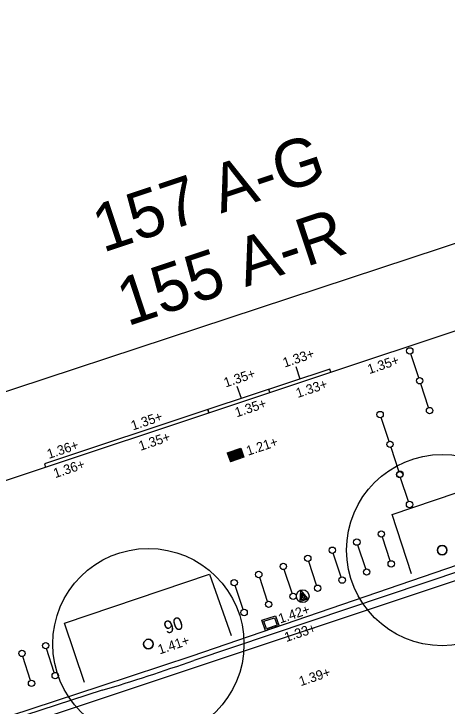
# Model space of a CAD drawing. Extents: x 122462 to 123306, y 485548 to 486417.
# Drawn here: x 122686.41 to 122700.01, y 486146.23 to 486167.94 of the extents above; entities that cross this region are included whole.
import ezdxf

# ---------------------------------------------------------------- set-up
doc = ezdxf.new("R2010")
doc.units = 0
for name, color, linetype in [('B-WE-AL-WERKGRENS-G', 7, 'Continuous'), ('B-WE-GR-BOOM-S', 7, 'Continuous'), ('B-WE-GR-BOOM_BOOMDIAMETER', 7, 'Continuous'), ('B-WE-IE-MEUBILAIR_WEGMEUBILAIR-S', 7, 'Continuous'), ('B-WE-IE-MEUBILAIR_WEGMEUBILAIR_FIETSNIETJE-S', 7, 'Continuous'), ('B-WE-OG-BEBOUWING_PORTIEK1-G', 7, 'Continuous'), ('B-WE-OG-BEBOUWING_RAAM-G', 7, 'Continuous'), ('B-WE-OG-HOOGTEPUNT-S', 7, 'Continuous'), ('B-WE-OG-TOPOKAART-G', 7, 'Continuous'), ('B-WE-RI-HWA_KOLK-S', 7, 'Continuous'), ('B-WE-VH-KANTOPSLUITING_OPSLUITBAND_100X200-G', 7, 'Continuous'), ('B-WE-VH-KANTOPSLUITING_TROTTOIRBAND_180 200-G', 7, 'Continuous'), ('B-WE-VH-MATERIAALGRENS_ASFALT-G', 7, 'Continuous'), ('B-WE-VW-MARKERING_LANGS_STREEP_11_010-G', 7, 'Continuous'), ('Level 58', 7, 'Continuous')]:
    doc.layers.add(name, color=color, linetype=linetype)

msp = doc.modelspace()

# ---------------------------------------------------------------- linework, layer by layer
at = {"layer": 'B-WE-AL-WERKGRENS-G'}
msp.add_lwpolyline([(122857.632, 486078.279), (122830.484, 486160.606), (122900.937, 486183.81), (122887.855, 486222.555), (122665.445, 486149.273), (122678.196, 486110.449), (122807.072, 486152.895), (122835.324, 486068.154)], dxfattribs=at)
at = {"layer": 'B-WE-GR-BOOM-S'}
for centre, radius in [((122699.849, 486151.122), 3), ((122690.629, 486148.177), 3), ((122699.849, 486151.122), 0.15), ((122690.629, 486148.177), 0.15)]:
    msp.add_circle(centre, radius, dxfattribs=at)
for centre, start, end in [((122699.849, 486151.122), 0, 180), ((122699.849, 486151.122), 180, 0), ((122690.629, 486148.177), 0, 180), ((122690.629, 486148.177), 180, 0)]:
    msp.add_arc(centre, 0.15, start, end, dxfattribs=at)
at = {"layer": 'B-WE-IE-MEUBILAIR_WEGMEUBILAIR-S'}
msp.add_lwpolyline([(122695.636, 486149.588), (122695.397, 486149.508), (122695.414, 486149.854), (122695.613, 486149.621), (122695.438, 486149.562), (122695.441, 486149.774), (122695.545, 486149.64), (122695.48, 486149.618), (122695.479, 486149.66), (122695.464, 486149.708)], dxfattribs=at)
msp.add_circle((122695.473, 486149.679), 0.2, dxfattribs=at)
at = {"layer": 'B-WE-IE-MEUBILAIR_WEGMEUBILAIR_FIETSNIETJE-S'}
for p, q in [((122699.112, 486156.53), (122698.864, 486157.276)), ((122699.423, 486155.594), (122699.175, 486156.34)), ((122698.181, 486154.534), (122697.933, 486155.281)), ((122698.492, 486153.598), (122698.244, 486154.344)), ((122698.794, 486152.649), (122698.546, 486153.395)), ((122698.217, 486150.787), (122697.971, 486151.533)), ((122697.448, 486150.532), (122697.201, 486151.279)), ((122696.679, 486150.278), (122696.432, 486151.025)), ((122695.909, 486150.024), (122695.663, 486150.771)), ((122695.14, 486149.77), (122694.893, 486150.517)), ((122694.371, 486149.516), (122694.124, 486150.263)), ((122693.601, 486149.262), (122693.354, 486150.009)), ((122687.676, 486147.283), (122687.436, 486148.033)), ((122686.932, 486147.039), (122686.692, 486147.788))]:
    msp.add_line(p, q, dxfattribs=at)
for centre in [(122698.833, 486157.371), (122699.143, 486156.435), (122699.143, 486156.435), (122699.454, 486155.499), (122697.902, 486155.375), (122698.212, 486154.439), (122698.212, 486154.439), (122698.515, 486153.49), (122698.523, 486153.503), (122698.825, 486152.554), (122697.939, 486151.628), (122697.17, 486151.374), (122696.401, 486151.12), (122695.631, 486150.866), (122698.249, 486150.692), (122694.862, 486150.612), (122697.479, 486150.437), (122694.092, 486150.358), (122693.323, 486150.104), (122696.71, 486150.183), (122695.941, 486149.929), (122695.171, 486149.675), (122694.402, 486149.421), (122693.633, 486149.167), (122687.406, 486148.128), (122686.662, 486147.884), (122687.706, 486147.188), (122686.962, 486146.944)]:
    msp.add_circle(centre, 0.1, dxfattribs=at)
at = {"layer": 'B-WE-OG-BEBOUWING_PORTIEK1-G'}
for p, q in [((122695.392, 486156.489), (122695.266, 486156.868)), ((122692.53, 486155.433), (122696.354, 486156.703)), ((122693.546, 486155.876), (122693.42, 486156.255)), ((122694.442, 486156.068), (122694.411, 486156.163))]:
    msp.add_line(p, q, dxfattribs=at)
msp.add_lwpolyline([(122692.53, 486155.433), (122696.354, 486156.703), (122696.323, 486156.798), (122692.499, 486155.528)], close=True, dxfattribs=at)
at = {"layer": 'B-WE-OG-BEBOUWING_RAAM-G'}
msp.add_lwpolyline([(122687.4, 486153.729), (122692.53, 486155.433), (122692.499, 486155.528), (122687.368, 486153.824)], close=True, dxfattribs=at)
at = {"layer": 'B-WE-OG-TOPOKAART-G'}
for points in [[(122696.354, 486156.703), (122704.132, 486159.286)], [(122683.995, 486152.598), (122687.4, 486153.729)]]:
    msp.add_lwpolyline(points, dxfattribs=at)
at = {"layer": 'B-WE-RI-HWA_KOLK-S'}
for p, q in [((122693.106, 486154.173), (122693.532, 486154.318)), ((122693.125, 486154.164), (122693.522, 486154.299)), ((122693.522, 486154.299), (122693.609, 486154.043)), ((122693.532, 486154.318), (122693.628, 486154.034)), ((122693.106, 486154.173), (122693.202, 486153.889)), ((122693.125, 486154.164), (122693.211, 486153.908)), ((122693.628, 486154.034), (122693.202, 486153.889)), ((122693.609, 486154.043), (122693.211, 486153.908)), ((122694.192, 486148.921), (122694.617, 486149.066)), ((122694.617, 486149.066), (122694.731, 486148.735)), ((122694.305, 486148.59), (122694.192, 486148.921)), ((122694.731, 486148.735), (122694.305, 486148.59)), ((122694.352, 486148.606), (122694.351, 486148.611)), ((122694.433, 486148.649), (122694.357, 486148.623)), ((122694.447, 486148.638), (122694.445, 486148.643)), ((122694.47, 486148.646), (122694.469, 486148.651)), ((122694.551, 486148.69), (122694.475, 486148.664)), ((122694.565, 486148.679), (122694.563, 486148.683)), ((122694.589, 486148.687), (122694.587, 486148.692)), ((122694.625, 486148.715), (122694.593, 486148.704)), ((122694.669, 486148.73), (122694.625, 486148.715)), ((122694.683, 486148.719), (122694.682, 486148.724))]:
    msp.add_line(p, q, dxfattribs=at)
for points in [[(122693.363, 486154.21), (122693.352, 486154.206)], [(122693.435, 486154.029), (122693.376, 486154.204)], [(122693.393, 486154.21), (122693.452, 486154.035)], [(122693.411, 486154.226), (122693.399, 486154.222)], [(122693.483, 486154.046), (122693.423, 486154.22)], [(122693.44, 486154.226), (122693.5, 486154.051)], [(122693.458, 486154.242), (122693.447, 486154.238)], [(122693.53, 486154.062), (122693.471, 486154.236)], [(122693.488, 486154.242), (122693.547, 486154.067)], [(122693.505, 486154.258), (122693.494, 486154.255)], [(122693.577, 486154.078), (122693.518, 486154.252)], [(122693.156, 486154.129), (122693.216, 486153.955)], [(122693.174, 486154.146), (122693.163, 486154.142)], [(122693.246, 486153.965), (122693.187, 486154.14)], [(122693.204, 486154.145), (122693.263, 486153.971)], [(122693.221, 486154.162), (122693.21, 486154.158)], [(122693.293, 486153.981), (122693.234, 486154.156)], [(122693.251, 486154.161), (122693.31, 486153.987)], [(122693.269, 486154.178), (122693.257, 486154.174)], [(122693.341, 486153.997), (122693.281, 486154.172)], [(122693.298, 486154.177), (122693.358, 486154.003)], [(122693.316, 486154.194), (122693.305, 486154.19)], [(122693.323, 486153.981), (122693.334, 486153.985)], [(122693.388, 486154.013), (122693.329, 486154.188)], [(122693.346, 486154.194), (122693.405, 486154.019)], [(122693.37, 486153.997), (122693.382, 486154.001)], [(122693.418, 486154.013), (122693.429, 486154.017)], [(122693.465, 486154.029), (122693.476, 486154.033)], [(122693.512, 486154.045), (122693.524, 486154.049)], [(122693.56, 486154.061), (122693.571, 486154.065)], [(122693.228, 486153.949), (122693.24, 486153.952)], [(122693.276, 486153.965), (122693.287, 486153.968)]]:
    msp.add_lwpolyline(points, dxfattribs=at)
msp.add_lwpolyline([(122694.255, 486148.89), (122694.586, 486149.003), (122694.667, 486148.766), (122694.336, 486148.653)], close=True, dxfattribs=at)
for centre, start, end in [((122693.355, 486154.197), 108.7699, 198.7699), ((122693.367, 486154.201), 18.7699, 108.7699), ((122693.403, 486154.213), 108.7699, 198.7699), ((122693.414, 486154.217), 18.7699, 108.7699), ((122693.45, 486154.229), 108.7699, 198.7699), ((122693.461, 486154.233), 18.7699, 108.7699), ((122693.497, 486154.245), 108.7699, 198.7699), ((122693.509, 486154.249), 18.7699, 108.7699), ((122693.166, 486154.132), 108.7699, 198.7699), ((122693.177, 486154.136), 18.7699, 108.7699), ((122693.213, 486154.149), 108.7699, 198.7699), ((122693.225, 486154.152), 18.7699, 108.7699), ((122693.261, 486154.165), 108.7699, 198.7699), ((122693.272, 486154.168), 18.7699, 108.7699), ((122693.284, 486153.978), 288.7699, 18.7699), ((122693.308, 486154.181), 108.7699, 198.7699), ((122693.32, 486153.99), 198.7699, 288.7699), ((122693.319, 486154.185), 18.7699, 108.7699), ((122693.331, 486153.994), 288.7699, 18.7699), ((122693.367, 486154.006), 198.7699, 288.7699), ((122693.378, 486154.01), 288.7699, 18.7699), ((122693.414, 486154.022), 198.7699, 288.7699), ((122693.426, 486154.026), 288.7699, 18.7699), ((122693.462, 486154.038), 198.7699, 288.7699), ((122693.473, 486154.042), 288.7699, 18.7699), ((122693.509, 486154.055), 198.7699, 288.7699), ((122693.521, 486154.058), 288.7699, 18.7699), ((122693.557, 486154.071), 198.7699, 288.7699), ((122693.568, 486154.074), 288.7699, 18.7699), ((122693.225, 486153.958), 198.7699, 288.7699), ((122693.236, 486153.962), 288.7699, 18.7699), ((122693.272, 486153.974), 198.7699, 288.7699), ((122694.36, 486148.614), 108.8786, 198.8786), ((122694.436, 486148.64), 18.8786, 108.8786), ((122694.478, 486148.654), 108.8786, 198.8786), ((122694.554, 486148.68), 18.8786, 108.8786), ((122694.597, 486148.695), 108.8786, 198.8786), ((122694.672, 486148.721), 18.8786, 108.8786)]:
    msp.add_arc(centre, 0.01, start, end, dxfattribs=at)
at = {"layer": 'B-WE-VH-KANTOPSLUITING_OPSLUITBAND_100X200-G'}
for points in [[(122698.891, 486150.381), (122698.277, 486152.242), (122700.968, 486153.154)], [(122688.628, 486146.971), (122687.999, 486148.836), (122692.548, 486150.369), (122693.222, 486148.443)], [(122691.993, 486147.799), (122689.134, 486146.852)]]:
    msp.add_lwpolyline(points, dxfattribs=at)
at = {"layer": 'B-WE-VH-KANTOPSLUITING_TROTTOIRBAND_180 200-G'}
for points in [[(122701.421, 486151.023), (122691.993, 486147.799)], [(122689.134, 486146.852), (122675.531, 486142.397), (122670.617, 486140.763)]]:
    msp.add_lwpolyline(points, dxfattribs=at)
at = {"layer": 'B-WE-VH-MATERIAALGRENS_ASFALT-G'}
for points in [[(122701.701, 486151.071), (122701.734, 486150.917), (122692.052, 486147.666)], [(122689.178, 486146.73), (122682.431, 486144.534), (122673.133, 486141.431), (122670.707, 486140.578), (122670.551, 486140.725)]]:
    msp.add_lwpolyline(points, dxfattribs=at)
msp.add_arc((122674.52, 486196.617), 51.996, 286.3738, 289.7049, dxfattribs=at)
at = {"layer": 'B-WE-VW-MARKERING_LANGS_STREEP_11_010-G'}
msp.add_lwpolyline([(122701.228, 486150.481), (122671.658, 486140.638)], dxfattribs=at)

# ---------------------------------------------------------------- texts
at = {"layer": 'B-WE-GR-BOOM_BOOMDIAMETER'}
msp.add_text('90', height=0.4, rotation=18.372, dxfattribs=at).set_placement((122691.194, 486148.484))
at = {"layer": 'B-WE-OG-HOOGTEPUNT-S'}
for s, rotation, p in [('1.33+', 18.372, (122694.905, 486156.847)), ('1.35+', 18.3766, (122697.562, 486156.641)), ('1.35+', 18.372, (122693.053, 486156.221)), ('1.33+', 18.372, (122695.316, 486155.893)), ('1.35+', 18.372, (122693.401, 486155.286)), ('1.35+', 18.372, (122690.14, 486154.874)), ('1.35+', 18.372, (122690.383, 486154.236)), ('1.36+', 18.372, (122687.505, 486153.982)), ('1.21+', 18.3766, (122693.758, 486154.081)), ('1.36+', 18.372, (122687.704, 486153.378)), ('1.42+', 18.4111, (122694.764, 486148.821)), ('1.33+', 18.4111, (122694.956, 486148.238)), ('1.41+', 18.4553, (122690.985, 486147.85)), ('1.39+', 18.4111, (122695.412, 486146.855))]:
    msp.add_text(s, height=0.3, rotation=rotation, dxfattribs=at).set_placement(p)
at = {"layer": 'Level 58'}
for s, p in [('157 A-G', (122689.2, 486160.444)), ('155 A-R', (122689.968, 486158.137))]:
    msp.add_text(s, height=1.5, rotation=18.3704, dxfattribs=at).set_placement(p)

doc.saveas('drawing.dxf')
